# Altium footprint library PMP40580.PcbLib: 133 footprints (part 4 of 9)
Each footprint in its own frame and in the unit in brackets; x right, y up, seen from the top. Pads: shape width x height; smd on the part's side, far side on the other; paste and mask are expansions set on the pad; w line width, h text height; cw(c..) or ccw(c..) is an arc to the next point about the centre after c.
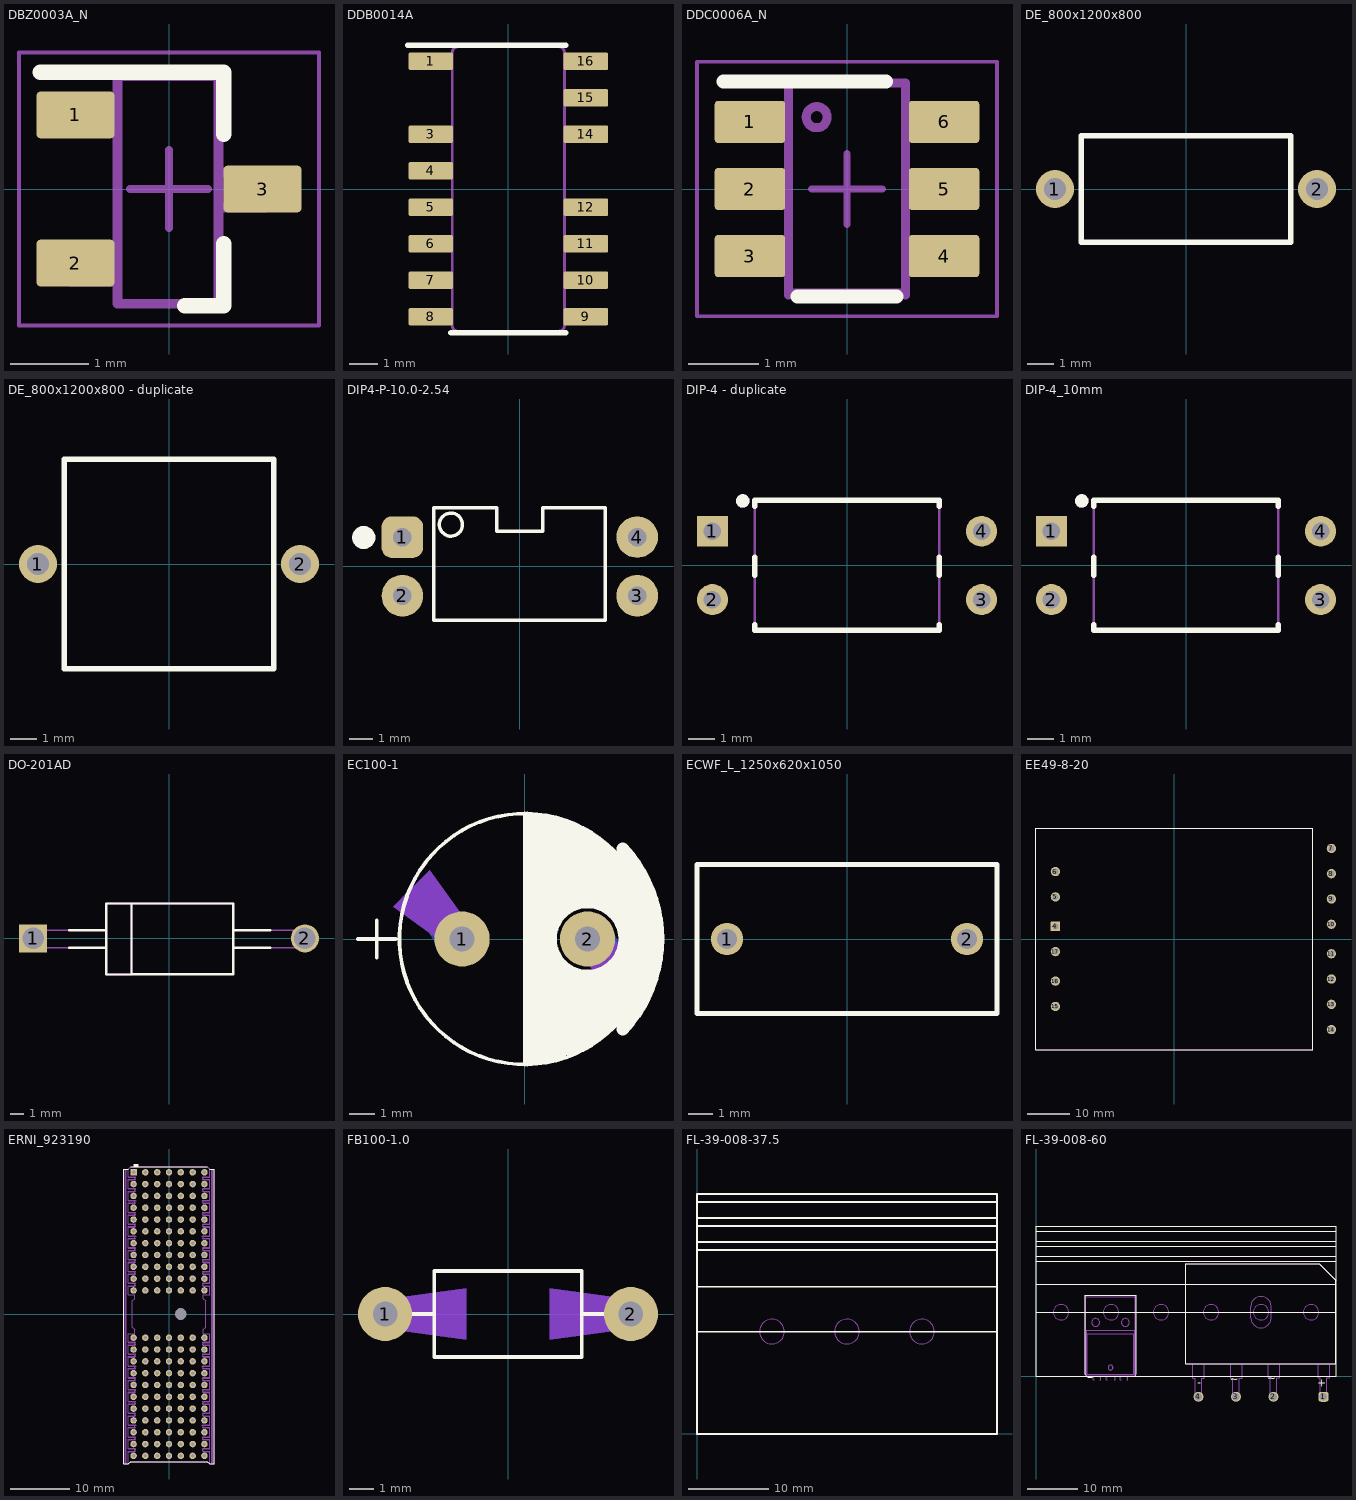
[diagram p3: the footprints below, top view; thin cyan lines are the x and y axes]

## DBZ0003A_N [mm] "SOT23, 3-Leads, Body 2.9x1.3mm, Pitch 0.95mm, Lead Span 2.4mm, IPC Medium Density"
height 1.12
pads (3):
  rrect17% 1x0.6 smd: 1(-1.2,0.95) 2(-1.2,-0.95) 3(1.2,0)
Top Overlay:
  lines w0.2: -1.651,1.5 0.7,1.5 0.7,0.7 ; 0.2,-1.5 0.7,-1.5 0.7,-0.7
Mechanical 5:
  lines w0.127: -1.27,-1.187 -1.27,-0.743 -1.063,-0.743 -1.005,-0.743 -0.814,-0.743 -0.66,-0.743 -0.66,-1.187 -0.814,-1.187 -1.005,-1.187 -1.063,-1.187 -1.27,-1.187 ; -1.27,0.718 -1.27,1.162 -1.063,1.162 -1.005,1.162 -0.814,1.162 -0.66,1.162 -0.66,0.718 -0.814,0.718 -1.005,0.718 -1.063,0.718 -1.27,0.718 ; -0.66,-1.473 -0.66,1.448 0.635,1.448 0.635,-1.473 -0.66,-1.473 ; 0.635,-0.235 0.789,-0.235 0.98,-0.235 1.037,-0.235 1.245,-0.235 1.245,0.21 1.037,0.21 0.98,0.21 0.789,0.21 0.635,0.21 0.635,-0.235
  text ".Designator" at -0.254,0.889 h0.51
Mechanical 15:
  lines w0.05: -1.925,-1.75 1.925,-1.75 1.925,1.75 -1.925,1.75 -1.925,-1.75
  lines w0.1: -0.5,0 0.5,0 ; 0,-0.5 0,0.5
3D body "DBZ0003A.stp": height 0.98, standoff 0, extent -1.257,-1.461 1.258,1.461

## DDB0014A [mm] "SMD, 14-Leads, Body 3.9x9.9mm, Pitch 1.27mm"
height 1.75
pads (14):
  rrect17% 1.55x0.6 smd: 1(-2.7,4.445) 3(-2.7,1.905) 4(-2.7,0.635) 5(-2.7,-0.635) 6(-2.7,-1.905) 7(-2.7,-3.175) 8(-2.7,-4.445) 9(2.7,-4.445) 10(2.7,-3.175) 11(2.7,-1.905) 12(2.7,-0.635) 14(2.7,1.905) 15(2.7,3.175) 16(2.7,4.445)
Top Overlay:
  lines w0.2: -3.5,5 2,5 ; -2,-5 2,-5
Mechanical 5:
  drawing of 288 lines, arcs and shapes, not listed
  text ".Designator" at -0.63,1.945 h1.85
3D body "DDB0014A.stp": height 1.75, standoff 0, extent -3.013,-4.95 3.013,4.95

## DDC0006A_N [mm]
height 1.1
pads (6):
  rrect17% 1x0.6 smd: 1(-1.375,0.95) 2(-1.375,0) 3(-1.375,-0.95) 4(1.375,-0.95) 5(1.375,0) 6(1.375,0.95)
Top Overlay:
  lines w0.2: -1.75,1.525 0.55,1.525 ; -0.7,-1.524 0.7,-1.524
Mechanical 5:
  lines w0.127: -0.828,-1.5 -0.828,1.5 0.828,1.5 0.828,-1.5 ; -0.825,-1.165 -1.437,-1.165 -1.437,-0.735 -0.825,-0.735 ; -0.825,-0.215 -1.437,-0.215 -1.437,0.215 -0.825,0.215 ; -0.825,0.735 -1.437,0.735 -1.437,1.165 -0.825,1.165 ; -0.754,-1.47 -0.75,-1.47 0.743,-1.47 0.747,-1.47 ; -0.754,1.5 -0.75,1.5 ; 0.743,1.5 0.747,1.5 ; 0.825,-1.165 1.437,-1.165 1.437,-0.735 0.825,-0.735 ; 0.825,-0.215 1.437,-0.215 1.437,0.215 0.825,0.215 ; 0.825,0.735 1.437,0.735 1.437,1.165 0.825,1.165 ; -0.578,1.018 ccw(c-0.43,1.018) -0.281,1.018 ccw(c-0.43,1.018) -0.578,1.018
  text ".Designator" at -0.246,2.641 h0.51
Mechanical 15:
  lines w0.05: -2.125,-1.8 -2.125,1.8 2.125,1.8 2.125,-1.8 -2.125,-1.8
  lines w0.1: -0.5,0 0.5,0 ; 0,-0.5 0,0.5
3D body "DDC0006A.stp": height 0.92, standoff 0, extent -1.434,-1.485 1.434,1.485

## DE_800x1200x800 [mm] "Murata"
height 12
pads (2):
  round 1.45 hole 0.85 paste+0 mask+0.05: 1(-5,0) 2(5,0)
Top Overlay:
  lines w0.2: -4,-2.032 -4,2.032 4,2.032 4,-2.032 -4,-2.032
Mechanical 5:
  lines w0.1: -4,-2.032 -4,2.032 4,2.032 4,-2.032 -4,-2.032
  text ".Designator" at -1.524,-0.508 h1.02
3D body: height 5, standoff -4, extent -5.298,-0.299 -4.7,0.3
3D body: height 5, standoff -4, extent 4.702,-0.299 5.3,0.3

## DE_800x1200x800 - duplicate [mm] "Murata"
height 12
pads (2):
  round 1.45 hole 0.85 paste+0 mask+0.05: 1(-5,0) 2(5,0)
Top Overlay:
  lines w0.2: -4,-4 -4,4 4,4 4,-4 -4,-4
Mechanical 5:
  lines w0.1: -4,-4 -4,4 4,4 4,-4 -4,-4
  text ".Designator" at -1.524,-0.508 h1.02
3D body: height 7.33, standoff 4.79, extent -5.21,-0.299 -2.666,0.3
3D body: height 5, standoff -4, extent -5.298,-0.299 -4.7,0.3
3D body: height 5, standoff -4, extent 4.702,-0.299 5.3,0.3
3D body: height 11.99, standoff 4.01, extent -4,-4 3.969,4
3D body: height 7.33, standoff 4.79, extent 2.666,-0.3 5.21,0.299

## DIP4-P-10.0-2.54 [mm]
pads (4):
  rrect50% 1.8x1.8 hole 0.8: 1(-5.08,1.27)
  round 1.8 hole 0.8: 2(-5.08,-1.27) 3(5.08,-1.27) 4(5.08,1.27)
Top Overlay:
  circle w0.5: c-6.75,1.25 r0.25
  circle w0.15: c-2.98,1.81 r0.5
  lines w0.15: -3.73,-2.33 -3.73,2.54 -1,2.54 -1,1.524 1,1.524 1,2.54 3.7,2.54 3.7,-2.33 -3.73,-2.33
Bottom Overlay:
  lines w0.254: -3.683,-0.762 -1.683,-0.762 ; -2.667,-1.524 -2.667,-0.742 ; -2.667,0.508 -2.667,1.397 ; -1.651,-0.127 -0.762,-1.016 ; -1.651,1.143 -0.762,0.254 ; -1.143,-1.016 -0.762,-1.016 ; -1.143,0.254 -0.762,0.254 ; -0.762,-0.635 -0.762,-1.016 ; -0.762,0.635 -0.762,0.254 ; 2.413,-1.651 2.413,1.524 ; 2.413,-0.508 3.556,-1.651 ; 2.413,0.381 3.556,1.524 ; 3.175,-1.651 3.556,-1.651 ; 3.556,-1.27 3.556,-1.651 ; -3.651,0.508 -2.683,-0.762 -1.651,0.508 -3.651,0.508
  lines w0.5: -5.969,0 -4.191,0 ; 4.191,0 5.969,0
3D body: height 3, standoff 2, extent 4.285,0.897 5.29,1.597
3D body: height 3, standoff 2, extent -5.29,0.897 -4.285,1.597
3D body: height 3, standoff 2, extent -5.29,-1.343 -4.285,-0.643
3D body: height 3, standoff 2, extent 4.275,-1.343 5.28,-0.643
3D body: height 5.59, standoff 0.51, extent -3.43,-2.288 3.43,2.542
3D body: height 0, standoff -2.5, extent -5.28,-1.343 -4.88,-0.943
3D body: height 0, standoff -2.5, extent -5.28,1.197 -4.88,1.597
3D body: height 0, standoff -2.5, extent 4.88,1.197 5.28,1.597
3D body: height 2, standoff 1.5, extent 4.89,0.897 5.29,1.597
3D body: height 2, standoff 0, extent 4.89,0.897 5.29,1.897
3D body: height 2, standoff 1.5, extent -5.29,1.197 -4.89,1.897
3D body: height 2, standoff 0, extent -5.29,0.897 -4.89,1.897
3D body: height 2, standoff 1.5, extent -5.29,-1.343 -4.89,-0.643
3D body: height 2, standoff 0, extent -5.29,-1.643 -4.89,-0.643
3D body: height 0, standoff -2.5, extent 4.88,-1.343 5.28,-0.943
3D body: height 2, standoff 0, extent 4.88,-1.643 5.28,-0.643
3D body: height 2, standoff 1.5, extent 4.88,-1.643 5.28,-0.943

## DIP-4 - duplicate [mm] "DIP, 4-Leads, Body 6.86x4.83mm, Pitch 2.54mm"
height 5.59
pads (4):
  rect 1.15x1.15 hole 0.65: 1(-5,1.27)
  round 1.15 hole 0.65: 2(-5,-1.27) 3(5,-1.27) 4(5,1.27)
Top Overlay:
  circle w0.25: c-3.875,2.395 r0.125
  lines w0.2: -3.43,-2.2 -3.43,-2.415 3.43,-2.415 3.43,-2.2 ; -3.43,-0.375 -3.43,0.3 ; -3.43,2.2 -3.43,2.415 3.43,2.415 3.43,2.2 ; 3.43,-0.375 3.43,0.3
Mechanical 5:
  circle w0.25: c-3.875,2.395 r0.125
  lines w0.1: -3.43,-2.415 3.43,-2.415 3.43,2.415 -3.43,2.415 -3.43,-2.415
  text ".Designator" at -1.15,-0.475 h1.02

## DIP-4_10mm [mm] "DIP, 4-Leads, Body 6.86x4.83mm, Pitch 2.54mm"
height 5.59
pads (4):
  rect 1.15x1.15 hole 0.65: 1(-5,1.27)
  round 1.15 hole 0.65: 2(-5,-1.27) 3(5,-1.27) 4(5,1.27)
Top Overlay:
  circle w0.25: c-3.875,2.395 r0.125
  lines w0.2: -3.43,-2.2 -3.43,-2.415 3.43,-2.415 3.43,-2.2 ; -3.43,-0.375 -3.43,0.3 ; -3.43,2.2 -3.43,2.415 3.43,2.415 3.43,2.2 ; 3.43,-0.375 3.43,0.3
Mechanical 5:
  circle w0.25: c-3.875,2.395 r0.125
  lines w0.1: -3.43,-2.415 -3.43,2.415 3.43,2.415 3.43,-2.415 -3.43,-2.415
  text ".Designator" at -1.15,-0.475 h1.02

## DO-201AD [mm] "Vishay dimensions"
height 5.5
pads (2):
  rect 2.1x2.1 hole 1.6: 1(-10.16,0)
  round 2.1 hole 1.6: 2(10.16,0)
Top Overlay:
  lines w0.178: -7.47,-0.7 -4.7,-0.7 ; -7.47,0.62 -4.7,0.62 ; -2.8,-2.69 4.8,-2.69 4.8,2.61 -2.8,2.61 ; 4.8,-0.7 7.57,-0.7 ; 4.8,0.62 7.57,0.62 ; -2.8,2.61 -2.8,-2.7 -4.7,-2.7 -4.7,2.61 -2.8,2.61
Mechanical 5:
  lines w0.127: -4.7,-0.7 -7.47,-0.7 -10.11,-0.7 cw(c-10.11,-0.04) -10.11,0.62 -7.47,0.62 -4.7,0.62 ; -2.8,-2.69 4.8,-2.69 4.8,2.61 -2.8,2.61 ; 4.8,-0.7 7.57,-0.7 10.21,-0.7 ccw(c10.21,-0.04) 10.21,0.62 7.57,0.62 4.8,0.62 ; -2.8,2.61 -4.7,2.61 -4.7,-2.7 -2.8,-2.7 -2.8,2.61
  text ".Designator" at -0.8,-0.2 h0.51
3D body "DO-201AD.stp": height 5.33, standoff -2.54, extent -10.819,-2.741 10.819,2.609

## EC100-1 [mm]
pads (2):
  round 2.2 hole 1: 1(-2.5,0) 2(2.5,0)
Top Layer keep-out:
  region: -3.988,2.55 -4.922,1.616 -2.869,-0.438 -2.744,-0.522 -2.522,-0.566 -2.3,-0.522 -2.112,-0.396 -1.987,-0.208 -1.943,0.013 -1.987,0.235 -2.111,0.421 -2.119,0.413
  region: 3.989,-2.55 4.922,-1.617 2.87,0.437 2.744,0.521 2.523,0.566 2.301,0.521 2.113,0.396 1.988,0.208 1.944,-0.014 1.988,-0.235 2.112,-0.422 2.119,-0.414
Bottom Layer:
  region: -3.96,0.487 -3.264,-0.611 -3.018,-0.783 -1.928,0.773 -2.174,0.945 -3.444,1.224
  region: 3.987,-0.492 3.291,0.606 3.045,0.778 1.955,-0.778 2.201,-0.95 3.471,-1.229
  region: -3.05,0.75 -3.05,0.849 -3.126,1.033 -3.267,1.174 -3.451,1.25 -3.55,1.25 -3.649,1.25 -3.833,1.174 -3.974,1.033 -4.05,0.849 -4.05,0.75 -4.05,0.651 -3.974,0.467 -3.833,0.326 -3.649,0.25 -3.55,0.25 -3.451,0.25 -3.267,0.326 -3.126,0.467 -3.05,0.651
  region: 4.05,-0.75 4.05,-0.651 3.974,-0.467 3.833,-0.326 3.649,-0.25 3.55,-0.25 3.451,-0.25 3.267,-0.326 3.126,-0.467 3.05,-0.651 3.05,-0.75 3.05,-0.849 3.126,-1.033 3.267,-1.174 3.451,-1.25 3.55,-1.25 3.649,-1.25 3.833,-1.174 3.974,-1.033 4.05,-0.849
Bottom Layer keep-out:
  region: -3.788,2.75 -5.253,1.285 -2.869,-0.437 -2.119,0.413
  region: 3.788,-2.75 5.253,-1.285 2.869,0.436 2.119,-0.414
Top Overlay:
  circle w0.15: c2.5,0 r1.3
  circle w0.15: c0,0 r5
  lines w0.15: -6.65,0 -5.15,0 ; -5.9,-0.75 -5.9,0.75 ; 0,-5 0,5 ; 0,-4.85 1.15,-4.85 ; 0,-4.7 1.6,-4.7 ; 0,-4.55 2.05,-4.55 ; 0,-4.4 2.35,-4.4 ; 0,-4.25 2.6,-4.25 ; 0,-4.1 2.8,-4.1 ; 0,-3.95 3,-3.95 ; 0,-3.8 3.2,-3.8 ; 0,-3.65 3.4,-3.65 ; 0,-3.5 3.55,-3.5 ; 0,-3.35 3.7,-3.35 ; 0,-3.2 3.8,-3.2 ; 0,-3.05 3.95,-3.05 ; 0,-2.9 4.05,-2.9 ; 0,-2.75 4.15,-2.75 ; 0,-2.6 4.25,-2.6 ; 0,-2.45 4.35,-2.45 ; 0,-2.3 4.4,-2.3 ; 0,-2.15 4.45,-2.15 ; 0,-2 4.55,-2 ; 0,-1.85 4.6,-1.85 ; 0,-1.7 4.65,-1.7 ; 0,-1.55 4.7,-1.55 ; 0,-1.4 4.7,-1.4 ; 0,-1.2 1.9,-1.2 ; 0,-1.1 1.7,-1.1 ; 0,-1 1.6,-1 ; 0,-0.9 1.5,-0.9 ; 0,-0.8 1.4,-0.8 ; 0,-0.7 1.3,-0.7 ; 0,-0.6 1.3,-0.6 ; 0,-0.5 1.3,-0.5 ; 0,-0.4 1.2,-0.4 ; 0,-0.3 1.2,-0.3 ; 0,-0.2 1.2,-0.2 ; 0,-0.1 1.2,-0.1 ; 0,0 1.1,0 ; 0,0.1 1.2,0.1 ; 0,0.2 1.2,0.2 ; 0,0.3 1.2,0.3 ; 0,0.4 1.2,0.4 ; 0,0.5 1.2,0.5 ; 0,0.6 1.3,0.6 ; 0,0.7 1.3,0.7 ; 0,0.8 1.4,0.8 ; 0,0.9 1.5,0.9 ; 0,1 1.6,1 ; 0,1.1 1.7,1.1 ; 0,1.2 1.9,1.2 ; 0,1.3 4.7,1.3 ; 0,1.4 4.8,1.4 ; 0,1.45 4.75,1.45 ; 0,1.6 4.7,1.6 ; 0,1.75 4.65,1.75 ; 0,1.9 4.6,1.9 ; 0,2.05 4.55,2.05 ; 0,2.2 4.45,2.2 ; 0,2.35 4.4,2.35 ; 0,2.5 4.3,2.5 ; 0,2.65 4.2,2.65 ; 0,2.8 4.1,2.8 ; 0,2.95 4,2.95 ; 0,3.1 3.9,3.1 ; 0,3.25 3.75,3.25 ; 0,3.4 3.65,3.4 ; 0,3.55 3.5,3.55 ; 0,3.7 3.35,3.7 ; 0,3.85 3.15,3.85 ; 0,4 2.95,4 ; 0,4.15 2.75,4.15 ; 0,4.3 2.5,4.3 ; 0,4.45 2.25,4.45 ; 0,4.6 1.95,4.6 ; 0,4.75 1.5,4.75 ; 0,4.9 0.9,4.9 ; 0.1,-1.3 2.2,-1.3 ; 2.9,-1.3 4.8,-1.3 ; 3.1,-1.2 4.8,-1.2 ; 3.1,1.2 4.8,1.2 ; 3.2,-1.1 4.8,-1.1 ; 3.3,1.1 4.8,1.1 ; 3.4,-1 4.8,-1 ; 3.4,1 4.8,1 ; 3.5,-0.9 4.8,-0.9 ; 3.5,0.9 4.9,0.9 ; 3.6,-0.8 4.9,-0.8 ; 3.6,-0.7 4.9,-0.7 ; 3.6,0.8 4.9,0.8 ; 3.7,-0.6 4.9,-0.6 ; 3.7,-0.5 4.9,-0.5 ; 3.7,0.5 4.9,0.5 ; 3.7,0.6 4.9,0.6 ; 3.7,0.7 4.9,0.7 ; 3.8,-0.4 4.9,-0.4 ; 3.8,-0.3 4.9,-0.3 ; 3.8,-0.1 5,-0.1 ; 3.8,0 5,0 ; 3.8,0.1 5,0.1 ; 3.8,0.2 4.9,0.2 ; 3.8,0.3 4.9,0.3 ; 3.8,0.4 4.9,0.4 ; 3.9,-0.2 4.9,-0.2
  lines w0.5: 3.896,-3.604 ccw(c0.004,0) 3.902,3.598
Bottom Overlay:
  lines w0.2: -1.75,-1.75 -0.75,-1.75 ; -1.25,-2.25 -1.25,-1.25 ; -0.6,-0.4 0.6,0.4 ; -0.6,0.4 0.6,1.2 0.6,-0.8 ; -0.6,0.8 -0.6,-1.2 0.6,-0.4

## ECWF_L_1250x620x1050 [mm] "TH, 2-Leads, Body 12.5x6.2mm, Pin Spacing 10mm"
height 10.5
pads (2):
  round 1.35 hole 0.85: 1(-5,0) 2(5,0)
Top Overlay:
  lines w0.2: -6.25,-3.1 6.25,-3.1 6.25,3.1 -6.25,3.1 -6.25,-3.1
Mechanical 5:
  lines w0.1: -6.25,-3.1 -6.25,3.1 6.25,3.1 6.25,-3.1 -6.25,-3.1
  text ".Designator" at -2,-0.7 h1.85
3D body: height 10.5, standoff 1.5, extent -6.25,-3.1 6.25,3.1
3D body: height 3, standoff 0, extent 4,-0.999 6,1
3D body: height 3, standoff 0, extent -6,-1 -4,1
3D body: height 0.5, standoff -2.5, extent 4.7,-0.299 5.3,0.3
3D body: height 0.5, standoff -2.5, extent -5.3,-0.3 -4.7,0.3

## EE49-8-20 [mm]
pads (14):
  rrect5% 2.2x2.2 hole 1.45 paste-1000 mask+0: 4(-28.25,3)
  round 2.2 hole 1.45 paste-1000 mask+0: 5(-28.25,10) 6(-28.25,16) 7(37.25,21.5) 8(37.25,15.5) 9(37.25,9.5) 10(37.25,3.5) 11(37.25,-3.5) 12(37.25,-9.5) 13(37.25,-15.5) 14(37.25,-21.5) 15(-28.25,-16) 16(-28.25,-10) 17(-28.25,-3)
Top Overlay:
  lines w0.2: -32.85,-26.25 -32.85,26.25 32.85,26.25 32.85,-26.25 -32.85,-26.25
Mechanical 5:
  lines w0.1: -32.85,-26.25 -32.85,26.25 32.85,26.25 32.85,-26.25 -32.85,-26.25
  text ".Designator" at 2.75,0 h0.5
3D body "UNK_EE49/8/20_PTH_64MM7_50MM5.STEP": height 0.25, standoff 0, extent -32.95,-26.35 38.45,26.35

## ERNI_923190 [mm] "Header(shrouded), 2mm, 154 Pos, TH"
height 13.45
pads (155):
  round 1.1 hole 0.6: A1(-4,24) A2(-4,22) A3(-4,20) A4(-4,18) A5(-4,16) A6(-4,14) A7(-4,12) A8(-4,10) A9(-4,8) A10(-4,6) A11(-4,4) A15(-4,-4) A16(-4,-6) A17(-4,-8) A18(-4,-10) A19(-4,-12) A20(-4,-14) A21(-4,-16) A22(-4,-18) A23(-4,-20) A24(-4,-22) A25(-4,-24) B1(-2,24) B2(-2,22) B3(-2,20) B4(-2,18) B5(-2,16) B6(-2,14) B7(-2,12) B8(-2,10) B9(-2,8) B10(-2,6) B11(-2,4) B15(-2,-4) B16(-2,-6) B17(-2,-8) B18(-2,-10) B19(-2,-12) B20(-2,-14) B21(-2,-16) B22(-2,-18) B23(-2,-20) B24(-2,-22) B25(-2,-24) C1(0,24) C2(0,22) C3(0,20) C4(0,18) C5(0,16) C6(0,14) C7(0,12) C8(0,10) C9(0,8) C10(0,6) C11(0,4) C15(0,-4) C16(0,-6) C17(0,-8) C18(0,-10) C19(0,-12) C20(0,-14) C21(0,-16) C22(0,-18) C23(0,-20) C24(0,-22) C25(0,-24) D1(2,24) D2(2,22) D3(2,20) D4(2,18) D5(2,16) D6(2,14) D7(2,12) D8(2,10) D9(2,8) D10(2,6) D11(2,4) D15(2,-4) D16(2,-6) D17(2,-8) D18(2,-10) D19(2,-12) D20(2,-14) D21(2,-16) D22(2,-18) D23(2,-20) D24(2,-22) D25(2,-24) E1(4,24) E2(4,22) E3(4,20) E4(4,18) E5(4,16) E6(4,14) E7(4,12) E8(4,10) E9(4,8) E10(4,6) E11(4,4) E15(4,-4) E16(4,-6) E17(4,-8) E18(4,-10) E19(4,-12) E20(4,-14) E21(4,-16) E22(4,-18) E23(4,-20) E24(4,-22) E25(4,-24) F1(6,24) F2(6,22) F3(6,20) F4(6,18) F5(6,16) F6(6,14) F7(6,12) F8(6,10) F9(6,8) F10(6,6) F11(6,4) F15(6,-4) F16(6,-6) F17(6,-8) F18(6,-10) F19(6,-12) F20(6,-14) F21(6,-16) F22(6,-18) F23(6,-20) F24(6,-22) F25(6,-24) Z2(-6,22) Z3(-6,20) Z4(-6,18) Z5(-6,16) Z6(-6,14) Z7(-6,12) Z8(-6,10) Z9(-6,8) Z10(-6,6) Z11(-6,4) Z15(-6,-4) Z16(-6,-6) Z17(-6,-8) Z18(-6,-10) Z19(-6,-12) Z20(-6,-14) Z21(-6,-16) Z22(-6,-18) Z23(-6,-20) Z24(-6,-22) Z25(-6,-24)
  round 0 hole 2 unplated: MH1(2,0)
  rect 1.1x1.1 hole 0.6: Z1(-6,24)
Top Overlay:
  rectangle: -6,25 -5.2,25.4
  lines w0.2: -6.9,24.525 -6.95,24.475 -7.2,24.475 -7.4,24.475 -7.7,24.475 -7.7,-25.375 -7.4,-25.375 -7.2,-25.375 -6.9,-25.375 -6.5,-24.975 6.5,-24.975 6.9,-25.375 7.2,-25.375 7.4,-25.375 7.7,-25.375 7.7,24.475 7.4,24.475 7.2,24.475 6.95,24.475 6.9,24.525 ; -6.45,24.975 6.45,24.975
Mechanical 5:
  drawing of 23300 lines, arcs and shapes, not listed
  text ".Designator" at -2,-0.7 h1.85
3D body "923190M.stp": height 13.45, standoff -3.8, extent -7.7,-25.375 7.7,24.975

## FB100-1.0 [mm]
pads (2):
  round 2.2 / inner round 2 / far side round 2.2 hole 1: 1(-5,0) 2(5,0)
Bottom Layer:
  region: 4.2,0 4.2,0.099 4.124,0.283 3.983,0.424 3.799,0.5 3.7,0.5 3.601,0.5 3.417,0.424 3.276,0.283 3.2,0.099 3.2,0 3.2,-0.099 3.276,-0.283 3.417,-0.424 3.601,-0.5 3.7,-0.5 3.799,-0.5 3.983,-0.424 4.124,-0.283 4.2,-0.099
  region: -3.2,0 -3.2,0.099 -3.276,0.283 -3.417,0.424 -3.601,0.5 -3.7,0.5 -3.799,0.5 -3.983,0.424 -4.124,0.283 -4.2,0.099 -4.2,0 -4.2,-0.099 -4.124,-0.283 -3.983,-0.424 -3.799,-0.5 -3.7,-0.5 -3.601,-0.5 -3.417,-0.424 -3.276,-0.283 -3.2,-0.099
  region: 3.5,-0.45 4.7,-0.95 5,-0.95 5,0.95 4.7,0.95 3.5,0.45
  region: -3.5,0.45 -4.7,0.95 -5,0.95 -5,-0.95 -4.7,-0.95 -3.5,-0.45
Bottom Layer keep-out:
  region: 5,0.6 1.7,0.6 1.7,-0.6 5,-0.612 5.234,-0.565 5.433,-0.433 5.565,-0.234 5.612,0 5.565,0.234 5.433,0.433 5.234,0.565 5,0.612
  region: -5,-0.6 -1.7,-0.6 -1.7,0.6 -5,0.612 -5.234,0.565 -5.433,0.433 -5.565,0.234 -5.612,0 -5.565,-0.234 -5.433,-0.433 -5.234,-0.565 -5,-0.612
  region: -1.7,-1.05 -1.7,1.05 -5,0.6 -5,-0.6
  region: 1.7,1.05 1.7,-1.05 5,-0.6 5,0.6
Top Overlay:
  lines w0.15: -5,0 -3,0 ; 3,0 5,0 ; -3,-1.75 3,-1.75 3,1.75 -3,1.75 -3,-1.75

## FL-39-008-37.5 [mm]
Top Overlay:
  lines w0.2: 0,12.8 37.5,12.8 ; 0,18.4 37.5,18.4 ; 0,23 37.5,23 ; 0,24 37.5,24 ; 0,26 37.5,26 ; 0,27 37.5,27 ; 0,29 37.5,29 ; 0,0 0,30 37.5,30 37.5,0 0,0
Mechanical 5:
  circle w0.1: c28.125,12.8 r1.55
  circle w0.1: c9.375,12.8 r1.55
  circle w0.1: c18.75,12.8 r1.55

## FL-39-008-60 [mm]
pads (4):
  rrect50% 2x2 hole 1.5: 1(57.5,-4.1)
  round 2 hole 1.5: 2(47.5,-4.1) 3(40,-4.1) 4(32.5,-4.1)
Top Overlay:
  rectangle: 10.3,-0.4 11.3,0
  lines w0.2: 0,12.8 60,12.8 ; 0,18.4 60,18.4 ; 0,23 60,23 ; 0,24 60,24 ; 0,26 60,26 ; 0,27 60,27 ; 0,29 60,29 ; 0,0 0,30 60,30 60,0 0,0 ; 9.8,0.4 9.8,16.2 20,16.2 20,0.4 19.8,0 18.4,0 10,0 9.8,0.4 ; 30,2.5 60,2.5 60,19.2 56.7,22.5 30,22.5 30,2.5
  text "+" at 58.1,-0.75 h1.52
  text "-" at 33.05,-0.775 h1.52
  text "~" at 48.075,0.225 h1.52
  text "~" at 40.525,-0.025 h1.52
Mechanical 5:
  circle w0.1: c55,12.8 r1.55
  circle w0.1: c45,12.8 r1.55
  circle w0.1: c35,12.8 r1.55
  circle w0.1: c15,12.8 r1.55
  circle w0.1: c25,12.8 r1.55
  circle w0.1: c5,12.8 r1.55
  circle w0.1: c15,12.8 r1.55
  lines w0.1: 11.66,-0.745 11.46,-0.745 11.46,-0.145 11.66,-0.145 11.66,0.055 12.76,0.055 12.76,-0.145 12.96,-0.145 12.96,-0.745 12.76,-0.745 ; 14.2,-0.713 14.003,-0.713 14.003,-0.145 14.2,-0.145 14.2,0.055 15.6,0.055 15.6,-0.145 15.8,-0.145 15.8,-0.745 15.6,-0.745 ; 17.04,-0.745 16.84,-0.745 16.84,-0.145 17.04,-0.145 17.04,0.055 18.14,0.055 18.14,-0.145 18.34,-0.145 18.34,-0.745 18.14,-0.745 ; 31.335,2.38 31.335,-0.37 31.875,-0.37 31.875,-3.4 31.875,-4.4 33.145,-4.4 33.145,-3.4 33.145,-0.37 33.685,-0.37 33.685,2.38 ; 38.95,2.4 38.95,-0.35 39.394,-0.35 39.394,-3.38 39.394,-4.38 40.664,-4.38 40.664,-3.38 40.664,-0.35 41.3,-0.35 41.3,2.4 ; 46.45,2.5 46.45,-0.25 46.894,-0.25 46.894,-3.28 46.894,-4.28 48.164,-4.28 48.164,-3.28 48.164,-0.25 48.8,-0.25 48.8,2.5 ; 47.05,12.8 47.05,12.9 ; 56.425,2.4 56.425,-0.35 56.869,-0.35 56.869,-3.38 56.869,-4.38 58.139,-4.38 58.139,-3.38 58.139,-0.35 58.775,-0.35 58.775,2.4 ; 9.81,16.187 9.81,0.338 9.983,0.055 10.017,0.055 ; 9.81,16.187 9.973,15.905 ; 9.81,16.187 9.95,16.205 19.85,16.205 19.99,16.187 ; 9.973,15.905 9.973,9.205 10.053,9.205 ; 9.973,15.905 19.827,15.905 ; 10.017,0.055 10.09,0.319 ; 10.017,0.055 19.783,0.055 ; 10.053,9.205 19.747,9.205 ; 10.053,9.205 10.09,8.647 ; 10.09,0.319 10.25,0.355 ; 10.09,0.319 10.09,8.647 ; 10.09,8.647 10.25,8.498 ; 10.25,0.355 10.25,8.498 ; 10.25,0.355 19.55,0.355 ; 10.25,8.498 19.55,8.498 ; 19.55,0.355 19.55,8.498 ; 19.55,0.355 19.71,0.319 ; 19.55,8.498 19.71,8.647 ; 19.71,0.319 19.71,8.647 ; 19.71,0.319 19.783,0.055 ; 19.71,8.647 19.747,9.205 ; 19.747,9.205 19.827,9.205 19.827,15.905 ; 19.783,0.055 19.817,0.055 19.99,0.338 19.99,16.187 ; 19.827,15.905 19.99,16.187 ; 11.132,10.767 ccw(c11.932,10.767) 12.732,10.767 ccw(c11.932,10.767) 11.132,10.767 ; 14.4,1.741 cw(c14.9,1.741) 15.4,1.741 cw(c14.9,1.741) 14.4,1.741 ; 17.068,10.767 ccw(c17.868,10.767) 18.668,10.767 ccw(c17.868,10.767) 17.068,10.767 ; 30,2.5 60,2.5 60,19.2 56.7,22.5 30,22.5 30,2.5 ; 42.95,11.74 ccw(c45,11.74) 47.05,11.74 47.05,13.9 ccw(c45,13.9) 42.95,13.9 42.95,11.74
